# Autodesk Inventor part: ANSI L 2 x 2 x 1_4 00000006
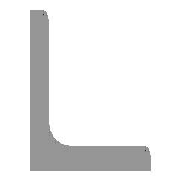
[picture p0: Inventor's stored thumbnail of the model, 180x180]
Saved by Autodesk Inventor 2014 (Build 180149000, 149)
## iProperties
_FrameMemberDoc: Frame Member File
_Version: 15.0.0
_CCFamilyMember: 11
_CCFamilyDisplayName: ANSI L (Equal angles) - Angle Steel
Created: 2007-02
Part Number: ANSI L 2 x 2 x 1_4 00000006
Material: Steel, Mild
Document SubType Name: Modeling
Standard: AISC
Designer: Autodesk, Inc.
Size Designation: L 2 x 2 x 1/4
Stock Number: L 2 x 2 x 1/4
Density: 7.86 g/cm^3
Description: Angle Steel
Standards Organization: ANSI
Language: en-US
Categories: <MemberInstance><Categories><Category DisplayName="Structural Shapes" InternalName="089c4875-fa83-4c05-b084-43b9cc11f5ed" Mnemonic="GRDR"><CategoryParameter Dis
Mass: 3370.01 g
Surface Area: 1403.81 cm^2
Volume: 428.754 cm^3
Appearance: Steel
IsCustomPart: 1
G_L: 28.000 in
G_W: 2.000 in
G_H: 2.000 in
+CC282AAB-4AD7-4025-8A75-6B04D7C1D3BB+CUTDETAIL1: Notch
+4B234BBB-5376-4DC8-859A-8989FA403DFD+CUTDETAIL2: Notch
Author: Autodesk, Inc.
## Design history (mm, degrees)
node "Start plane"
node "End plane"
sketch "Sketch"
  geometry: L1 (50.8, 0)-(0, 0); L2 (0, 0)-(0, 50.8); L3 (0, 50.8)-(3.302, 50.8); L4 (6.35, 47.752)-(6.35, 12.7); L5 (12.7, 6.35)-(47.752, 6.35); L6 (50.8, 3.302)-(50.8, 0); L7 (0, -11.041)-(0, 31.538); L8 (-11.041, 0)-(31.538, 0); L9 (0, 63.926)-(0, -23.536) reference; L10 (-23.536, 0)-(63.926, 0) reference; A1 r 6.35 centre (12.7, 12.7) between (6.35, 12.7) and (12.7, 6.35); A2 r 3.048 centre (3.302, 47.752) between (6.35, 47.752) and (3.302, 50.8); A3 r 3.048 centre (47.752, 3.302) between (50.8, 3.302) and (47.752, 6.35); 3 further points
  constraints: 16 end point, 6 point on circle, 6 point on line, 6 tangent, 4 parallel, 3 centre point, 2 collinear, 1 equal radius, 1 horizontal, 1 perpendicular
  dimensions: "d0" = 50.8 distance between parallel lines of L6 L2 (= G_H); "d1" = 50.8 distance between parallel lines of L3 L1 (= G_H); "d2" = 6.35 distance between parallel lines of L2 L4 (= G_T); "d3" = 6.35 distance between parallel lines of L1 L5 (= G_T); "d10" = 0 distance between parallel lines of L7 L2 (computed from ex); "d11" = 0 distance between parallel lines of L8 L1 (computed from d10); "d14" = 6.35 radius of A1 (= G_IR); "d15" = 3.048 radius of A2 (= G_ER)
extrude "Body" new body sketch "Sketch" stored distance "d4" = 711.2 (= G_L); taper "d5" = 0 deg
node "Driven Length"
  sketch "Sketch5"
    geometry: L1 (0, 0)-(10, 0) reference
    constraints: 2 end point, 1 horizontal
  workplane "Work Plane7"
  sketch "Sketch6"
    geometry: L1 (-2, 0)-(12, 0) reference; L2 (-2, 711.2)-(12, 711.2) reference
    dimensions: "d21" = 711.2 distance between parallel lines of L1 L2 (derived)
workplane "Work Plane3"
workplane "Work Plane4"
workplane "Work Plane5"
workplane "Work Plane6"
workplane "Work Plane8"
workplane "Work Plane9"
body "Solid1"
sketch "Sketch_1"
  geometry: L1 (50.8, 0)-(0, 0); L2 (0, 0)-(0, 50.8); L3 (0, 50.8)-(3.302, 50.8); L4 (6.35, 47.752)-(6.35, 12.7); L5 (12.7, 6.35)-(47.752, 6.35); L6 (50.8, 3.302)-(50.8, 0); A1 r 3.048 centre (3.302, 47.752) between (6.35, 47.752) and (3.302, 50.8); A2 r 6.35 centre (12.7, 12.7) between (6.35, 12.7) and (12.7, 6.35); A3 r 3.048 centre (47.752, 3.302) between (50.8, 3.302) and (47.752, 6.35)
  constraints: 12 end point, 6 point on circle, 3 centre point
extrude "Extrusion2" cut sketch "Sketch_1" stored distance "d22" = 3.302; taper "d23" = 0 deg
sketch "Sketch_2"
  geometry: L1 (50.8, 0)-(0, 0); L2 (0, 0)-(0, 50.8); L3 (0, 50.8)-(3.302, 50.8); L4 (6.35, 47.752)-(6.35, 12.7); L5 (12.7, 6.35)-(47.752, 6.35); L6 (50.8, 3.302)-(50.8, 0); A1 r 3.048 centre (3.302, 47.752) between (6.35, 47.752) and (3.302, 50.8); A2 r 6.35 centre (12.7, 12.7) between (6.35, 12.7) and (12.7, 6.35); A3 r 3.048 centre (47.752, 3.302) between (50.8, 3.302) and (47.752, 6.35)
  constraints: 12 end point, 6 point on circle, 3 centre point
extrude "Extrusion3" cut sketch "Sketch_2" stored distance "d24" = 3.302; taper "d25" = 0 deg
other parameters: "G_H" = 50.8 [user parameter; used in 2 equation terms], "G_T" = 6.35 [user parameter; used in 2 equation terms], "G_ER" = 3.048 [user parameter; used in 1 equation term], "G_IR" = 6.35 [user parameter; used in 1 equation term], "G_L" = 711.2 (= d21) [user parameter; used in 1 equation term], "ex" = 0 [user parameter; used in 1 equation term], "G_OFFSET_START" = 0 [user parameter; used in 1 equation term], "G_OFFSET_END" = 0 [user parameter; used in 1 equation term], "d12" = 0 (computed from G_OFFSET_START), "d13" = 711.2 (= G_OFFSET_END + B_L), "B_L" = 711.2 [user parameter; used in 1 equation term], "d20" = 90 deg
